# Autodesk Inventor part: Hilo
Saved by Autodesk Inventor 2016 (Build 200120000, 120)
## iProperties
Created: 2017-06
Part Number: Hilo
Material: Generic
Document SubType Name: Modeling
Designer: Administrator
Appearance: Generic
Author: Administrator
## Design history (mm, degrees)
feature "Body1"
body "Solid1"
